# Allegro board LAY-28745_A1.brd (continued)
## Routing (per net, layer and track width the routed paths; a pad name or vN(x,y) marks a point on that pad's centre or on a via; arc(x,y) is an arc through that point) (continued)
DIO2: length 31.1
  TOP w0.152: U1.51 46.84,21.6 v1(46.82,21.62) ; R129.1 v1(49.24,43.97) 49.24,43.96 51.74,43.96 52.22,43.48 52.22,42.31 51.14,41.23 J18.3 51.14,39.24 50,38.1 50,33.68 v1(50.83,32.85)
  BOTTOM w0.152: v1(46.82,21.62) 46.82,21.88 48.22,23.27 48.22,25.48 50.83,28.09 v1(50.83,32.85) ; v1(49.24,43.97) TP45.1
DIO3: length 26.4
  TOP w0.152: v1(47.71,40.67) 47.71,39.27 v1(49.11,37.87) ; R130.1 v1(47.71,43.97) ; U1.52 46.34,21.09 v1(46.32,21.11)
  BOTTOM w0.152: v1(47.71,43.97) TP44.1 v1(47.71,40.67) ; v1(49.11,37.87) 49.36,37.62 49.36,32.51 48.76,31.9 48.76,27.5 47.76,26.5 47.76,23.34 46.32,21.89 v1(46.32,21.11)
DIO4: length 55.7
  TOP w0.152: v1(47.84,37.87) 46.95,38.76 v1(46.95,40.67) ; R131.1 v1(46.19,43.97) ; v1(59.78,44.73) 62.7,41.81 62.7,32.03 J10.1 ; U1.53 45.84,21.59 v1(45.81,21.62)
  BOTTOM w0.152: v1(47.84,37.87) 47.84,35.46 47.59,35.2 47.59,33.61 48.13,33.07 48.13,32.38 48.48,32.03 48.48,27.62 47.49,26.62 47.49,23.55 45.81,21.87 v1(45.81,21.62) ; v1(46.95,40.67) 46.95,42.19 TP43.1 v1(46.19,43.97) 46.95,44.73 53.05,44.73 53.56,44.22 54.06,44.22 54.57,44.73 v1(59.78,44.73)
DIO5/CLKOUT: length 12
  TOP w0.152: v1(45.3,21.11) 45.34,21.07 U1.54
  BOTTOM w0.152: v1(45.3,21.11) 45.3,19.35 44.5,18.56 44.5,15.34 43.2,14.04 41.15,14.04 TP42.1 41.11,12.85
EXTAL_32M: length 10.7
  TOP w0.152: C20.1 53.56,24.41 51.97,24.41 C21.1 49.79,25.04 Y1.1 49.35,24.7 48.35,23.7 48.35,22.44 49.34,21.45 U1.46
IO_REF: length 124.2
  TOP w0.203: U5.1 v1(3.77,24.92)
  TOP w0.305: U16.19 43.4,42.01 v1(43.4,44.73) ; U17.19 54.58,42.83 54.57,42.83 C62.1 v1(53.81,44.73)
  TOP w0.381: v1(41.11,45.75) 41.11,44.73 R125.1 41.62,44.73 C48.1 v1(43.4,44.73) ; R20.2 v1(8.85,26.44) ; R21.1 v1(7.07,22.63) ; v1(30.95,25.3) v1(27.9,25.3) ; R126.1 41.36,40.69 v1(41.84,41.16) ; v1(27.9,8.85) 27.9,12.85 v1(29.17,14.12) R139.1 R138.1 ; C64.1 v1(3.77,24.92)
  PWR w0.381: v1(41.84,41.16) 41.84,41.34 41.97,41.47 41.97,42.33 41.36,42.94 41.36,43.22 40.87,43.71 31.46,43.71 30.95,43.21 v1(30.95,42.7)
  BOTTOM w0.381: v1(27.9,8.85) 27.9,3.84 J3.4 ; v1(27.9,25.3) 12.41,25.3 11.26,26.44 v1(8.85,26.44) 7.96,25.55 7.96,23.52 v1(7.07,22.63) 6.31,21.87 4.28,21.87 3.77,22.38 v1(3.77,24.92) ; v1(30.95,42.7) v1(30.95,25.3) 30.95,22.57 31.2,22.31 31.2,16.03 R138.1 R139.1 v1(29.17,14.12) ; v1(43.4,44.73) 44.41,44.73 45.55,45.87 52.67,45.87 v1(53.81,44.73) ; v1(41.11,45.75) 41.11,45.24 42.77,43.58 42.77,42.1 v1(41.84,41.16)
P5-9V_VIN: length 28.9
  TOP w0.406: 38.06,6.63 38.06,1.8 38.7,1.17 40.47,1.17 J3.16 40.6,3.84 40.6,6.63
  TOP w0.813: J7.1 29.15,10.67 D1.A 29.2,7.95 C38.1 C39.1 C6.1 36.74,7.95 38.06,6.63 40.6,6.63
PA_BOOST: length 1.1
  TOP w0.203: U1.41 L12.1
PA_BOOST_EXT: length 4.5
  TOP w0.457: C1.1 L1.2 60.28,21.11 C2.1 60.29,21.11 C47.1
POWER_EN: length 6.3
  TOP w0.152: R551.1 26.44,44.16 26.44,42.28 26.45,42.27 26.45,41.61 v1(26.63,41.43) ; v1(26.63,40.39) U6.31
  BOTTOM w0.152: v1(26.63,41.43) v1(26.63,40.39)
PTA0/SWD_CLK: length 27.7
  TOP w0.152: U1.10 42.43,15.16 v1(42.28,15.31) ; v1(48.73,32.61) 48.29,32.17 48.29,30.44 J35.1 49.03,28.27 v1(47.45,28.27)
  BOTTOM w0.152: SH1.2 47.97,35.08 47.97,34.32 TP36.1 48.48,32.87 v1(48.73,32.61) ; v1(42.28,15.31) 43.53,16.55 43.53,18.96 43.66,19.1 43.66,19.1 44.06,19.5 44.06,22.48 44.52,22.95 45.48,22.95 46.58,24.05 46.58,26.59 46.58,26.59 46.58,27.4 v1(47.45,28.27)
PTA1/UART0_RX: length 53.3
  TOP w0.152: J41.2 60.67,30.76 60.67,32.28 62.19,33.81 v1(62.19,34.82) ; v1(32.79,37.49) 32.66,37.62 29.11,37.62 28.41,36.92 R89.2
  BOTTOM w0.152: v1(62.19,34.82) SH15.2 ; v1(32.79,37.49) 33.49,36.79 34.57,36.79 35.65,37.87 36.92,37.87 38.37,39.32 49.1,39.32 49.44,39.66 50.52,39.66 50.74,39.45 51.85,39.45 52.64,40.23 54.52,40.23 56.75,38 56.75,34.55 56.86,34.44 56.86,33.47 57.71,32.62 59.64,32.62 59.93,32.33 59.93,30.29 58.89,29.25 J41.2 TP113.1
PTA2/UART0_TX: length 44.6
  TOP w0.152: R88.2 31.71,36.6 v1(32.79,36.6) ; J42.1 57.87,33.05 60.03,33.05 60.67,33.68 v1(60.67,34.82)
  BOTTOM w0.152: v1(32.79,36.6) 33.24,36.16 35.78,36.16 36.09,36.47 36.09,37.17 36.41,37.49 36.98,37.49 38.53,39.04 49.19,39.04 49.52,38.71 50.29,38.71 50.47,38.89 51.49,38.89 52.22,38.16 52.22,34.51 54.44,32.28 55.59,32.28 J42.1 57.06,30.81 57.06,30.81 57.35,30.52 57.35,28.01 56.41,27.08 TP114.1 ; v1(60.67,34.82) SH16.2
PTA3/SWD_DIO: length 61.8
  TOP w0.152: v1(46,40.67) 46.57,40.09 v1(46.57,37.87) ; J14.2 v1(31.33,13.23) R25.1 ; U1.11 43.06,14.66 v1(42.9,14.49) 42.87,14.52 41.65,14.52 41.54,14.63 37.43,14.63 37.05,14.25 37.05,12.03 36.54,11.52 v1(33.62,11.52) ; R92.2 v1(37.55,45.75)
  BOTTOM w0.152: J14.2 33.62,13.11 v1(33.62,11.52) ; R25.1 v1(31.33,13.23) ; v1(42.9,14.49) 44.16,15.76 44.16,18.71 44.69,19.24 44.69,19.25 44.79,19.35 44.79,21.3 47.21,23.71 47.21,26.74 48.2,27.73 48.2,31.87 47.84,32.23 47.84,32.84 47.21,33.47 SH7.2 46.76,35.59 46.57,35.78 v1(46.57,37.87) ; v1(37.55,45.75) 37.55,44.48 38.06,43.97 40.28,43.97 40.7,43.56 40.7,41.08 41.07,40.7 45.96,40.7 v1(46,40.67)
PTA4/NMI: length 62.9
  TOP w0.152: v1(39.47,9.02) 39.49,9.04 41.24,9.04 R133.1 42.56,9.09 42.56,13.44 43.28,14.16 U1.12 ; v1(9.1,7.15) 9.09,7.14 R558.2 C53.1 SW4.1
  BOTTOM w0.152: v1(39.47,9.02) 39.47,7.61 38.09,6.24 38.09,1.95 37.67,1.52 18.26,1.52 12.46,7.32 12.46,10.05 11.55,10.97 11.55,10.97 11.49,11.03 7.34,11.03 6.8,10.49 6.8,7.74 7.41,7.14 TP29.1 9.09,7.14 v1(9.1,7.15)
PTA18: length 4.2
  TOP w0.152: U1.15 44.33,12.52 44.33,12.1 43.72,11.49 43.38,11.49 v1(43.23,11.34)
  BOTTOM w0.152: SH45.2 41.46,11.49 43.08,11.49 v1(43.23,11.34)
PTA19: length 83
  TOP w0.152: v1(42.63,8.36) 42.63,8.36 42.65,8.36 42.65,8.38 42.67,8.4 43.39,8.4 R136.1 43.78,8.79 43.78,11.06 44.84,12.12 U1.16
  BOTTOM w0.152: TP115.1 36.79,32.28 36.95,32.13 36.95,32.12 37.65,31.42 37.65,13.34 37.65,13.33 37.65,11.9 39.78,9.77 39.78,9.77 40.89,8.66 40.89,8.66 41.19,8.36 v1(42.63,8.36) 42.88,8.36 44.47,6.78 44.47,6.77 44.66,6.59 44.66,4.65 45.62,3.69 50.42,3.69 51,4.27 51,5.81 51.96,6.77 52.84,6.77 54.7,8.64 54.7,12.37 54.21,12.87 53.76,12.87 52.38,14.25 52.06,14.25 51.75,14.56 51.75,17.4 52.76,18.41 54.74,18.41 55.16,18 56.13,18 56.91,18.78 56.91,19.3 57.5,19.89 60.32,19.89 62.71,22.28 62.71,28.06 62.19,28.58 J10.2
PTB0: length 37.4
  TOP w0.152: R29.2 v1(36.54,31.52) ; U1.17 45.34,12.19 44.16,11.01 44.16,9.17 44.67,8.66 44.67,8.66 R132.1 44.01,7.5 v1(44.01,6.59)
  BOTTOM w0.152: v1(44.01,6.59) 44.01,6.59 44.01,6.59 44.02,6.59 44.02,6.6 43.99,6.6 43.99,6.6 44.02,6.6 44.02,6.63 42.75,7.91 41.25,7.91 40.84,8.31 40.84,8.31 40.84,8.32 40.78,8.38 40.77,8.38 39.5,9.65 39.5,9.65 39.5,9.65 37.37,11.79 37.37,13.45 37.37,13.45 37.37,29.67 TP120.1 v1(36.54,31.52)
PTB1: length 79
  TOP w0.152: R28.2 37.35,33.61 37.35,34.1 37.76,34.51 38.38,34.51 38.78,34.11 38.78,33.53 39.29,33.02 41.7,33.02 41.96,33.28 42.41,33.28 42.76,32.93 42.76,32.46 42.67,32.38 42.67,32.38 42.63,32.34 42.63,32.34 42.43,32.13 42.43,28.18 42.99,27.62 44.94,27.62 45.48,28.17 45.48,29.38 46.04,29.95 47.64,29.95 47.93,30.24 47.93,32.52 48.49,33.08 48.91,33.08 49.64,33.81 49.64,38.7 v1(50.1,39.17) 50.1,41.91 J18.4 ; U1.18 45.84,13.01 46.06,13.23 47.43,13.23 47.74,13.54 47.74,15.54 48.29,16.09 v2(48.22,16.09)
  BOTTOM w0.152: v1(50.1,39.17) 52.06,39.17 52.84,39.95 54.41,39.95 55.61,38.75 55.61,37.32 55.47,37.18 55.47,35.81 55.7,35.59 SH11.2 TP121.1 57.65,32.26 57.65,27.2 56.18,25.74 55.27,25.74 55.06,25.54 53.49,25.54 53.49,25.54 53.11,25.54 53.11,25.54 50.62,25.54 49.75,24.66 49.75,21.03 47.68,18.96 47.68,18.96 47.68,16.64 v2(48.22,16.09)
PTB2: length 67.8
  TOP w0.152: v2(49.25,16.12) 48.84,15.71 48.45,15.71 48.02,15.28 48.02,13.41 47.34,12.73 U1.21 ; v1(32.79,35.59) 31.71,35.59 R91.2
  BOTTOM w0.152: v2(49.25,16.12) 49.25,16.33 49.09,16.5 49.09,17.43 49.49,17.84 49.49,18.43 49.41,18.51 49.41,18.97 50.4,19.95 51.44,19.95 53.39,21.9 53.81,21.9 54.44,22.54 54.44,24.09 55.46,25.11 58,25.11 59.64,26.75 59.64,28.2 60.21,28.77 60.21,32.44 59.75,32.9 58.53,32.9 TP123.1 SH12.2 57.24,35.59 57.03,35.79 57.03,38.12 54.64,40.52 52.56,40.52 51.7,41.38 50.74,41.38 48.96,39.6 36.61,39.6 35.9,38.89 34.89,38.89 34.51,39.27 33.55,39.27 32.28,38 32.28,36.09 v1(32.79,35.59)
PTB17: length 74.2
  TOP w0.152: v1(32.79,34.7) 29.04,34.7 R90.2 ; v2(48.73,14.19) 48.3,13.75 48.3,13.2 47.84,12.73 U1.22
  BOTTOM w0.152: v1(32.79,34.7) 31.97,35.52 31.97,38.25 33.36,39.65 34.63,39.65 35.01,39.27 35.8,39.27 36.41,39.88 48.85,39.88 50.62,41.66 51.88,41.66 52.72,40.83 54.73,40.83 57.24,38.32 58.62,38.32 59.79,37.15 59.79,35.78 59.59,35.59 SH14.2 TP122.1 59.26,33.81 60.49,32.57 60.49,28.64 59.93,28.09 59.93,27.33 60.21,27.05 60.21,23.64 58.15,21.57 53.46,21.57 50.21,18.33 50.21,17.99 49.37,17.14 49.37,16.61 49.68,16.3 49.68,15.94 49.17,15.43 49.17,14.63 v2(48.73,14.19)
PTC1: length 41.9
  TOP w0.152: v1(62.2,27.79) 61.97,27.79 61.56,28.2 59.74,28.2 59.32,27.77 55.78,27.77 54.57,28.98 v1(54.57,32.85) ; R97.2 54.06,12.22 v1(54.08,12.23)
  BOTTOM w0.152: v1(54.08,12.23) 53.9,12.23 53.11,13.02 53.11,13.03 52.23,13.9 51.92,13.9 51.41,14.41 51.41,17.55 52.62,18.76 54.89,18.76 55.31,18.34 55.98,18.34 56.57,18.92 56.57,19.45 57.39,20.27 60.21,20.27 62.36,22.42 62.36,27.6 62.19,27.77 62.19,27.79 v1(62.2,27.79) ; v1(54.57,32.85) TP112.1 SH10.2
PTC1/RTC_IN: length 5.8
  TOP w0.152: R97.1 52.61,10.76 52.28,10.76 52.27,10.77 50.77,10.77 50.65,10.65 49.7,10.65 49.19,11.16 49.19,11.56 48.84,11.91 U1.24
PTC2: length 122.2
  TOP w0.152: v1(62.19,38.82) 62,39.01 59.08,39.01 58.53,38.46 54.59,38.46 v1(54.57,38.44) ; v1(54.49,6.7) 54.47,6.7 54.47,6.77 54.14,7.1 54.14,7.89 53.61,8.42 v1(53.61,8.55) ; v1(9.1,10.18) 9.09,10.19 R557.2 C52.1 6.31,10.19 5.85,10.64 SW3.1 ; U1.25 49.34,13.01 49.56,13.23 50.63,13.23 50.81,13.41 50.81,14.81 50.72,14.9 50.72,14.92 50.6,15.04 50.58,15.04 v2(50.43,15.19)
  BOTTOM w0.152: TP24.1 9.09,10.19 v1(9.1,10.18) 9.1,10.18 9.67,10.75 11.37,10.75 12.16,9.96 12.16,7.19 15,4.34 15,4.32 18.15,1.18 53.26,1.18 53.6,1.52 53.6,5.91 54.39,6.7 v1(54.49,6.7) ; SH9.2 53.56,35.59 53.87,35.9 53.87,37.62 54.57,38.32 v1(54.57,38.44) ; v1(53.61,8.55) 53.48,8.67 53.48,9.51 52.65,10.34 52.65,12.6 52.49,12.76 52.49,12.77 51.97,13.28 51.66,13.28 50.58,14.36 50.58,14.66 50.43,14.82 v2(50.43,15.19) 50.78,15.54 50.78,17.89 53.89,21 59.45,21 60.79,22.34 60.79,27.32 61,27.52 61,28.35 60.79,28.55 60.79,32.66 59.92,33.54 59.92,35.05 60.12,35.25 60.12,37.61 59.96,37.77 59.96,38.49 60.29,38.82 v1(62.19,38.82)
PTC3: length 5.3
  TOP w0.152: v1(49.74,11.68) 49.84,11.78 U1.26
  BOTTOM w0.152: SH40.2 47.71,9.58 47.48,9.81 47.48,10.29 48.16,10.98 48.16,11.48 48.44,11.76 49.66,11.76 v1(49.74,11.68)
PTC4: length 5.2
  TOP w0.152: U1.23 48.34,11.72 48.73,11.33 v1(48.73,11.3)
  BOTTOM w0.152: SH41.2 48.2,8.15 48.72,8.68 48.72,11.29 v1(48.73,11.3)
PTD4/SPI1_PCS0: length 45
  TOP w0.152: U1.27 50.34,11.8 50.34,11.8 50.34,11.14 v1(50.34,11.13)
  BOTTOM w0.152: SH3.2 45.94,34.98 46.92,33.99 46.92,33.35 47.55,32.73 47.55,32.12 47.92,31.75 47.92,27.85 46.93,26.86 46.93,23.89 45.62,22.58 44.73,22.58 44.46,22.31 44.46,22.3 44.4,22.25 44.4,19.35 43.87,18.82 43.87,16.12 42.49,14.74 40.74,14.74 40.56,14.56 40.55,14.56 40.14,14.15 40.14,11.9 40.94,11.1 40.97,11.1 40.99,11.08 42.7,11.08 46.23,7.55 48.12,7.55 49.18,8.61 49.18,9.97 v1(50.34,11.13)
PTD5/SPI1_SCK: length 45.7
  TOP w0.152: v1(50.91,11.71) 50.84,11.78 U1.28
  BOTTOM w0.152: SH6.2 44.67,35.22 45.38,34.5 45.38,33.01 45.04,32.67 45.04,28.73 41.55,25.24 41.55,19.32 42.35,18.52 42.35,16.68 41,15.33 40.45,15.33 39.57,14.46 39.57,11.66 40.76,10.47 42.07,10.47 42.07,10.47 42.48,10.47 45.98,6.96 49.28,6.96 49.51,7.19 49.51,9.18 v1(50.11,9.78) 50.61,10.28 50.61,10.28 51.08,10.75 51.08,11.54 v1(50.91,11.71)
PTD6/LLWU_P15: length 99.6
  TOP w0.152: R134.1 53.02,7.93 v1(53.18,7.93) ; v1(39.27,29.05) 39.25,29.03 39.25,27.95 39,27.7 39,27.7 38.95,27.65 37.16,27.65 36.95,27.86 36.11,27.86 34.95,26.7 v1(27.94,26.7) ; v1(52.03,11.33) 51.46,11.9 51.46,12.51 51.46,12.51 51.46,13.07 51.46,13.07 U1.29 ; SW1.1 5.85,47.09 6.44,46.51 C51.1 R556.2 8.5,46.51 9,46.01 v1(9.04,46.01)
  BOTTOM w0.152: v1(27.94,26.7) 27.4,27.24 13.69,27.24 9.98,30.94 9.98,38.56 9.04,39.5 v1(9.04,46.01) 9.04,46.04 8.49,45.49 TP23.1 ; v1(39.27,29.05) 39.27,28.57 38.65,27.95 38.65,11.29 41.11,8.83 42.81,8.83 42.98,8.66 42.98,8.66 44.75,6.89 44.75,6.89 44.94,6.7 44.94,4.77 45.73,3.97 50.3,3.97 50.71,4.37 50.71,5.92 51.95,7.16 52.4,7.16 53.17,7.93 ; 53.17,7.93 53.17,7.94 53.17,8.16 53.18,8.17 53.18,8.36 52.54,9 52.53,9 52.35,9.19 52.35,11.01 v1(52.03,11.33) ; 53.17,7.93 v1(53.18,7.93)
PTD7: length 108.7
  TOP w0.152: U1.31 52,14.16 52.27,13.89 52.27,13.89 52.56,13.6 v1(53.68,13.6) ; SW2.1 6.36,42.19 C54.1 R559.2 v1(11.78,42.19) ; v1(62.19,39.52) 62,39.33 57.52,39.33 57.5,39.35 v1(57.19,39.35) 57.2,39.33 v1(53.87,39.33)
  BOTTOM w0.152: v1(53.68,13.6) 53.6,13.68 53.6,13.74 52.79,14.55 52.19,14.55 52.03,14.71 52.03,17.29 52.88,18.14 54.49,18.14 54.92,17.7 56.23,17.7 57.19,18.67 57.19,19.16 57.64,19.61 60.43,19.61 62.99,22.16 62.99,28.32 63.27,28.6 63.27,32.35 62.95,32.66 62.95,38.76 v1(62.19,39.52) ; TP30.1 v1(11.78,42.19) 13.49,42.19 14.48,43.18 15.83,43.18 18.38,45.73 20.17,45.73 20.24,45.79 20.62,45.79 20.68,45.73 22.6,45.73 23.03,46.16 29.78,46.16 30.21,46.59 35.86,46.59 36.22,46.23 36.22,44.01 38.22,42.01 39.29,42.01 41.14,40.16 48.73,40.16 50.52,41.95 52.12,41.95 52.12,41.95 52.13,41.95 52.13,41.94 52.13,41.93 52.14,41.92 52.14,41.92 52.15,41.9 52.16,41.9 52.25,41.81 52.25,41.8 52.34,41.72 52.34,41.72 52.93,41.13 54.86,41.13 56.3,39.69 56.85,39.69 v1(57.19,39.35) ; SH8.2 v1(53.87,39.33)
PTE0/SPI1_MISO: length 54.5
  TOP w0.152: v1(54.05,14.22) 54.03,14.21 52.79,14.21 52.34,14.66 U1.32 ; v1(51.79,7.96) 51.79,7.27 v1(52.79,6.27)
  BOTTOM w0.152: v1(51.79,7.96) 51.39,8.36 50.13,8.36 49.87,8.09 49.87,7.04 49.45,6.62 45.83,6.62 42.96,9.49 41.37,9.49 40.66,10.2 40.64,10.2 39.28,11.55 39.28,14.56 40.34,15.62 40.86,15.62 42.07,16.83 42.07,18.4 41.4,19.07 40.78,19.07 40.1,19.74 40.1,25.68 42.7,28.27 42.7,28.31 42.74,28.35 42.74,30.38 43.87,31.52 J44.1 ; v1(52.79,6.27) 52.79,6.33 55,8.53 55,13.46 54.24,14.22 v1(54.05,14.22)
PTE1/SPI1_MOSI: length 37.5
  TOP w0.152: v1(50.17,16.08) 50.59,15.66 U1.34 ; J43.2 46.44,28.36 47.19,27.62 50.26,27.62 52.57,29.93 52.63,29.93 52.65,29.95 53.48,29.95 54.06,29.36 54.06,28.99 55.67,27.39 60.23,27.39 60.48,27.64 v1(60.48,27.74)
  BOTTOM w0.152: v1(50.17,16.08) 50.17,16.57 50.49,16.89 50.49,18.04 53.75,21.29 58.3,21.29 60.52,23.51 60.52,27.67 60.48,27.71 v1(60.48,27.74)
PTE16: length 92.7
  TOP w0.152: v1(42.85,17.67) 43.25,17.67 43.26,17.66 U1.5 ; v1(48.68,7.42) 48.68,7.59 R137.1 50.06,8.98 50.52,8.98 50.54,9 53.41,9 53.42,9 53.8,9 53.8,9 54.15,9 v1(54.21,8.93) ; R11.2 v1(33.49,33.17)
  BOTTOM w0.152: v1(33.49,33.17) 33.49,34.44 33.93,34.89 37.93,34.89 v1(38.38,35.33) 38.38,37.06 38.88,37.57 43.06,37.57 43.84,38.35 44.82,38.35 45.39,37.78 45.39,34.93 45.68,34.64 45.68,32.89 45.34,32.55 45.34,28.6 41.83,25.09 41.83,19.43 42.85,18.42 v1(42.85,17.67) 42.86,17.66 42.86,16.78 41.13,15.05 40.6,15.05 39.85,14.31 39.85,11.78 40.87,10.76 42.6,10.76 46.11,7.25 48.51,7.25 v1(48.68,7.42) ; TP119.1 61.18,26.7 61.18,21.97 59.83,20.62 57.24,20.62 56.22,19.6 56.22,19.06 55.84,18.68 55.45,18.68 55.03,19.1 52.47,19.1 51.06,17.7 51.06,15.42 51.06,15.42 51.06,14.28 51.78,13.56 52.09,13.56 52.77,12.88 52.77,12.88 52.95,12.7 52.95,10.51 54.04,9.42 54.04,9.1 v1(54.21,8.93)
PTE17: length 48.1
  TOP w0.152: v1(41.28,18.37) 42.49,17.16 U1.6 ; v1(50.33,7.91) 50.83,8.41 R135.1 ; v1(42.25,32.73) 42.25,32.72 39.14,32.72 38.06,33.8 R30.2
  BOTTOM w0.152: v1(42.25,32.73) 42.42,32.56 42.42,28.39 39.81,25.78 39.81,19.2 40.65,18.37 v1(41.28,18.37) 41.51,18.13 41.51,16.7 40.72,15.91 40.15,15.91 38.97,14.73 38.97,11.37 41.19,9.15 42.89,9.15 43.1,8.94 43.1,8.94 45.24,6.8 45.24,6.8 45.72,6.31 49.73,6.31 50.33,6.91 v1(50.33,7.91)
PTE18/I2C0_SDA: length 27.2
  TOP w0.152: v1(40.09,36.09) R119.1 40.09,38.13 R117.2 ; v1(41.04,17.47) 41.09,17.47 41.89,16.66 43.71,16.66 U1.7 ; v1(41.36,32.03) 41.25,31.92 Q1.S2
  BOTTOM w0.152: v1(40.09,36.09) 40.22,35.97 40.22,33.17 v1(41.36,32.03) 41.36,27.76 39.53,25.92 39.53,18.97 41.04,17.47 v1(41.04,17.47)
PTE19/I2C0_SCL: length 31.2
  TOP w0.152: v1(39.33,35.33) R118.1 40.09,34.06 R116.2 ; v1(40.74,16.85) 40.93,16.85 41.62,16.15 42.38,16.15 42.38,16.16 U1.8 ; v1(39.84,29.74) 39.97,29.62 39.97,28.71 Q1.S1 39.95,28.12 39.03,27.2 v1(36.54,27.2)
  BOTTOM w0.152: v1(40.74,16.85) 40.74,16.85 40.52,17.07 40.52,17.38 39.24,18.65 39.24,26.05 40.46,27.26 40.46,29.12 v1(39.84,29.74) 39.33,30.25 v1(39.33,35.33)
PTE30: length 2.3
  TOP w0.152: U1.9 42.58,15.66 42.47,15.76 42.09,15.76 41.99,15.66 41.5,15.66 R85.1
RESET_B_TGTMCU: length 6.7
  TOP w0.152: U6.21 23.58,36.22 24.6,35.2 26.63,35.2 27.27,34.57 27.27,33.68 J11.2
RESET_B_XCVR: length 24
  TOP w0.152: R5.1 42.51,24.98 44.59,27.06 51.32,27.06 v1(52.03,27.77) ; U1.48 48.34,21.1 v1(48.35,21.11)
  BOTTOM w0.152: J31.1 52.03,30.51 v1(52.03,27.77) 51.9,27.77 49.14,25.01 49.14,21.9 v1(48.35,21.11)
RESET_TGTMCU_B: length 110.1
  TOP w0.152: J9.3 3.26,22.12 R14.2 ; J14.10 33.49,24.92 32.47,25.93 v1(27.27,25.93) ; 21.81,24.73 22.76,24.73 23.2,25.17 v1(23.2,25.93) ; 21.81,24.73 D5.C ; 21.81,24.73 R13.2 21.3,22.63 U3.7 ; v1(52.6,15.11) 52.55,15.16 U1.33 ; R124.1 5.8,26.7 v1(5.8,26.44) U5.7 ; v1(38.19,8.41) 39.69,8.41 v1(40.05,8.05)
  BOTTOM w0.152: v1(27.27,25.93) v1(23.2,25.93) 13.8,25.93 12.53,27.2 6.57,27.2 v1(5.8,26.44) 5.3,26.95 3.52,26.95 3.26,26.7 TP35.1 J9.3 ; v1(52.6,15.11) 52.92,15.43 53.7,15.43 54.98,14.15 54.98,13.87 55.28,13.58 55.28,13.35 55.28,13.34 55.28,8.42 53.29,6.43 53.29,1.81 52.98,1.5 40.97,1.5 40.63,1.83 40.63,5.77 40.04,6.36 40.04,8.04 v1(40.05,8.05) ; J14.10 32.79,18.31 31.84,17.36 31.84,12.79 33.11,11.52 33.11,8.85 33.55,8.41 v1(38.19,8.41)
RFIO: length 1.1
  TOP w0.203: U1.39 L9.1
RFIO_EXT: length 8.6
  TOP w0.203: C7.1 L2.2 59.52,15.4 C4.1
  TOP w0.457: C4.1 C50.1
RXTX: length 41.9
  TOP w0.152: R141.1 v1(58.51,43.97) ; U1.37 52.55,17.16 v1(52.72,17.33)
  BOTTOM w0.152: v1(58.51,43.97) 58.52,43.98 60.92,43.98 63.92,40.98 63.92,21.28 61.25,18.61 57.71,18.61 55.83,16.73 55.45,16.73 54.75,17.42 TP37.1 52.82,17.42 v1(52.72,17.33)
SDA_EXTAL: length 3.9
  TOP w0.152: U6.17 21.55,36.74 21.55,36.09 C31.1 20.66,35.2 20.66,34.04 Y3.3
SDA_JTAG_TCLK: length 11.9
  TOP w0.152: U6.12 20.93,39.37 v1(19.77,39.37)
  BOTTOM w0.152: v1(19.77,39.37) 18.99,39.37 18.76,39.14 18.76,38.63 19.27,38.13 19.27,36.98 18.76,36.47 18.76,32.92 TP509.1 J13.4
SDA_JTAG_TDI: length 14.6
  TOP w0.152: U6.13 19.27,38.89 v1(19.27,38.89)
  BOTTOM w0.152: v1(19.27,38.89) 20.03,38.89 20.28,38.63 20.28,31.9 TP511.1 J13.8
SDA_JTAG_TDO: length 11.2
  TOP w0.152: U6.14 19.79,38.39 v1(19.77,38.38)
  BOTTOM w0.152: J13.6 TP510.1 19.14,32.03 19.14,36.35 19.77,36.98 v1(19.77,38.38)
SDA_JTAG_TMS: length 12.2
  TOP w0.152: J13.2 16.09,36.86 R107.2 ; U6.15 19.28,37.89 19.27,37.87 v1(18.76,37.87)
  BOTTOM w0.152: v1(18.76,37.87) 18.76,36.98 18.38,36.6 18.38,33.81 TP508.1 J13.2
SDA_LED: length 3.7
  TOP w0.152: v1(27.52,40.41) 27.52,39.78 27.14,39.4 D11.C 27.12,39.39 U6.29
  BOTTOM w0.152: TP106.1 27.52,39.52 v1(27.52,40.41)
SDA_RST: length 16.3
  TOP w0.152: v1(24.09,31.27) R100.1 R52.2 23.58,34.32 v1(23.58,34.82) 23.58,34.95 22.58,35.95 U6.19
  BOTTOM w0.152: J13.10 TP512.1 18.76,29.11 21.93,29.11 v1(24.09,31.27) ; TP105.1 v1(23.58,34.82)
SDA_RST_TGTMCU_J_B: length 43
  TOP w0.152: R14.1 4.53,21.87 7.07,21.87 J9.1 9.36,21.62 v1(16.09,21.62) ; R16.2 v1(20.03,18.82) 20.66,18.19 22.44,18.19 23.33,19.08 23.33,21.74 23.96,22.38 26.5,22.38 27.01,22.89 27.01,24.03 27.52,24.54 v1(29.43,24.54) ; v1(20.03,20.09) 20.9,20.09 U3.2
  BOTTOM w0.152: J11.1 29.43,28.98 v1(29.43,24.54) ; v1(16.09,21.62) 16.09,20.47 16.47,20.09 v1(20.03,20.09) v1(20.03,18.82)
SDA_SPI0_SCK: length 13.6
  TOP w0.152: U4.12 34.89,42.63 34.89,38.51 34.44,38.06 27.58,38.06 v1(27.39,37.87) 25.73,37.87 U6.26
SDA_SPI0_SIN: length 17.4
  TOP w0.152: v1(34.25,40.67) 34.25,39.9 33.11,38.76 26.44,38.76 26.31,38.89 U6.28 ; R112.1 37.47,43.89 U4.8 37.43,42.64 v1(37.43,40.67)
  BOTTOM w0.152: v1(37.43,40.67) v1(34.25,40.67)
SDA_SPI0_SOUT: length 11.7
  TOP w0.152: v1(34.25,38.63) 34.06,38.44 25.73,38.44 U6.27 ; v1(34.25,37.49) 34.25,35.67 U4.2
  BOTTOM w0.152: v1(34.25,37.49) v1(34.25,38.63)
SDA_SWD_EN: length 23.1
  TOP w0.152: U6.16 20.79,37.39 v1(20.79,36.6) ; v1(28.41,40.41) 30.44,40.41 R106.2 v1(34.25,41.43) 34.22,41.46 U4.13 ; v1(36.16,41.43) 36.17,41.44 U4.10
  BOTTOM w0.152: v1(36.16,41.43) v1(34.25,41.43) ; v1(20.79,36.6) 21.17,36.22 27.77,36.22 28.41,36.86 v1(28.41,40.41)
SDA_SWD_OE_B: length 17.8
  TOP w0.152: U4.1 33.57,34.14 33.24,33.81 v1(32.79,33.81) R105.1 31.71,32.03 31.33,31.65 27.27,31.65 26.89,32.03 26.89,34.32 26.38,34.82 24.47,34.82 23.08,36.22 23.08,36.74 U6.20
SDA_USB_CONN_DN: length 24.7
  TOP w0.292: v1(23.47,45) 23.56,44.92 23.56,44.45 R50.1 ; v1(10.91,34.98) 10.94,34.98 10.94,35.06 10.88,35 10.56,35 U12.1 9.61,34.93 8.76,34.93 8.58,35.12 J15.2
  BOTTOM w0.292: v1(10.91,34.98) 10.93,34.98 10.92,34.97 10.92,34.97 10.93,34.96 11.26,34.96 11.65,35.35 11.65,36.15 14.7,39.2 14.7,39.2 18.5,43 18.5,43 18.59,43.09 19.98,43.09 19.98,43.09 20.47,43.09 20.47,43.09 21.04,43.09 22.18,41.94 22.82,41.94 23.6,42.72 23.6,43.07 23.61,43.07 23.61,44.87 v1(23.47,45)
SDA_USB_CONN_DP: length 25.4
  TOP w0.292: v1(24.13,45) 24.13,44.94 24.04,44.85 24.04,44.53 R51.1 ; J15.3 8.58,34.32 8.77,34.5 9.57,34.5 U11.1 10.12,33.99 10.52,34.38 10.87,34.38 v1(10.93,34.32)
  BOTTOM w0.292: v1(24.13,45) 24.04,44.91 24.04,42.54 23,41.51 22,41.51 20.86,42.65 18.77,42.65 15.14,39.02 15.14,39.02 12.09,35.97 12.09,35.17 11.42,34.5 11.2,34.5 11.02,34.32 v1(10.93,34.32)
SDA_USB_DN: length 1.8
  TOP w0.254: U6.4 23.58,41.92 23.63,41.97 23.63,42.9 R50.2
SDA_USB_DP: length 1.8
  TOP w0.254: R51.2 24.03,42.89 24.03,41.97 24.08,41.92 U6.3
SDA_USB_VOUT33: length 48
  TOP w0.203: C32.1 21.55,43.69 21.85,43.99 21.85,44.2 21.84,44.2 21.84,44.41 v1(21.83,44.42) ; C32.1 21.55,42.41 22.08,41.88 U6.7 ; C32.1 22.24,43.46 23.08,42.62 U6.5 ; C29.1 19.27,20.65 19.47,20.85 U3.1 ; v1(19.27,39.9) 19.28,39.89 U6.11
  TOP w0.254: v1(24.85,42.45) 24.85,42.34 25.08,42.11 U6.1
  TOP w0.305: 19.27,19.46 20.54,19.46 20.79,19.2 R19.2 ; 19.27,19.46 18.25,19.46 ; 19.27,19.46 C29.1 ; 18.25,19.46 R16.1 ; 18.25,19.46 17.21,19.46
  TOP w0.406: U4.14 33.57,42.7 v1(32.73,42.7) ; U4.4 v1(35.52,36.86)
  TOP w0.508: C66.1 v1(19.27,39.9) ; R17.1 v1(32.35,39.4) ; R105.2 v1(29.3,33.81) ; J13.1 v1(14.82,34.57) ; R106.1 v1(29.17,41.43) R110.1 ; v1(24.85,42.45) 24.86,42.45 25.36,42.95 C26.1 ; R107.1 14.82,36.86 v1(14.82,35.84)
  TOP w0.762: v3(17.49,36.86) 18,36.35 18,27.27 17.21,26.48 D7.A
  PWR w0.508: 13.46,34.3 J13.1
  BOTTOM w0.508: v1(24.85,42.45) 24.85,42.44 TP103.1
SDA_USBSHIELD: length 19.8
  TOP w0.508: v1(4.91,29.87) 4.91,29.87 ; J15.S3 1.86,39.97 ; J15.S3 1.86,37.56 ; J15.S3 3.32,38.77 ; 9.91,29.03 L7.1 ; L7.1 9.04,30 ; L7.1 9.91,30.96 ; J15.S2 7.36,31.07 ; J15.S2 8.82,29.87 ; J15.S2 7.36,28.66 ; J15.S2 5.9,29.87 ; 7.36,37.56 J15.S1 ; J15.S1 7.36,39.97 ; J15.S1 5.9,38.77 ; J15.S4 3.32,29.87 ; J15.S4 1.86,31.07 ; J15.S4 1.86,28.66
SDA_XTAL: length 10.3
  TOP w0.152: U6.18 22.08,35.86 21.3,35.08 21.3,31.01 22.5,29.81 ; Y3.1 22.5,29.81 ; 22.5,29.81 22.5,30.18 22.82,30.51 C30.1
SW1_RST_B: length 6.4
  TOP w0.152: R113.2 C60.1 5.85,17.3 ; 5.85,17.3 5.85,20.6 J9.2 ; 5.85,17.3 SW5.1
SWD_CLK_TGTMCU: length 63.5
  TOP w0.152: v1(31.52,24.54) 31.84,24.22 31.84,15.39 32.73,14.5 J14.4 ; v1(34.25,45.75) R93.2 ; v1(38.06,41.43) v1(38.06,37.87)
  BOTTOM w0.152: J35.2 49.75,38 49.05,38.7 43.7,38.7 42.92,37.92 38.11,37.92 v1(38.06,37.87) ; v1(38.06,41.43) 35.87,43.62 35.87,45.14 R93.2 v1(34.25,45.75) 31.52,43.01 v1(31.52,24.54)
SWD_CLK_TGTMCU_R: length 4.9
  TOP w0.152: R93.1 35.52,44.48 U4.11 v1(35.52,39.9)
SWD_DIO_TGTMCU: length 10.4
  TOP w0.152: R92.1 36.82,44.73 U4.9 36.79,42.64 v1(36.79,38.63) 36.03,38.63 34.87,37.48 U4.3
TC_EXTAL_TP: length 5
  TOP w0.152: U6.10 19.73,40.39 19.2,40.92 v1(18.5,40.92)
  BOTTOM w0.152: TP102.1 19.01,40.41 v1(18.5,40.92)
TC_SDA_USB_ID_TP: length 2.7
  TOP w0.152: v1(5.8,33.55) 7.45,33.55 J15.4
  BOTTOM w0.152: TP100.1 v1(5.8,33.55)
TC_XTAL_TP: length 2.9
  TOP w0.152: v1(19.65,41.68) 19.65,41.24 19.99,40.89 U6.9
  BOTTOM w0.152: TP101.1 v1(19.65,41.68)
UART1_CTS_TGTMCU: length 5
  TOP w0.152: U6.22 24.08,36.23 24.73,35.59 27.14,35.59 R90.1 27.39,35.2 v1(27.9,34.7)
UART1_RST_TGTMCU: length 6.7
  TOP w0.152: U6.23 24.58,36.24 24.92,35.9 28.73,35.9 v1(29.3,35.33) R91.1
UART1_RX_TGTMCU: length 1.9
  TOP w0.152: U6.25 26.1,37.39 v1(26.63,36.86) R89.1
UART1_TX_TGTMCU: length 6
  TOP w0.152: U6.24 25.08,36.44 25.3,36.22 28.66,36.22 v1(29.3,36.86) R88.1
V_EXT: length 2.8
  TOP w0.813: D2.A 20.28,7.88 J28.1
V_MCU: length 41.9
  TOP w0.203: U3.8 20.9,21.62 v1(20.03,21.62)
  TOP w0.254: C43.1 46.34,11.73 U1.19 ; v1(44.92,22.12) 44.92,21.59 44.67,21.34 44.67,20.98 44.84,20.81 U1.55
  TOP w0.305: v1(56.35,13.87) 56.3,13.91 Y4.1 ; Y4.12 57.16,13.91 v1(57.11,13.87)
  TOP w0.508: v1(36.41,13.23) J14.1 34.76,12.66 34.32,12.22 29.81,12.22 29.3,12.73 R25.2 ; R13.1 C35.1 C59.1 v1(20.03,21.62) ; R9.2 39.6,23.54 40.94,23.54 v1(40.98,23.58) R5.2 ; C43.1 v1(45.17,11.33) ; v1(44.92,22.12) C42.1 43.84,22.12 v1(43.4,21.68) 42.13,21.68 C27.1 ; R18.2 v1(19.27,23.9) ; R113.1 v1(9.11,16.28)
  PWR w0.457: v1(9.11,16.28) 15.07,16.28
  PWR w0.508: 24.38,24.63 J40.1 ; J40.1 26.34,22.67 ; J40.1 24.38,22.67 ; J40.1 26.34,24.63
  BOTTOM w0.508: TP6.1 J40.1 ; SH42.1 v1(43.4,21.68)
V_RF: length 7.8
  TOP w0.203: v1(52.49,16.16) 52.49,16.16 U1.35
  TOP w0.254: v1(51.39,20.6) 51.15,20.6 U1.43
  TOP w0.508: C19.1 52.99,16.66 52.87,16.54 52.85,16.54 52.83,16.52 52.79,16.52 52.76,16.49 52.74,16.49 52.61,16.36 52.61,16.34 52.58,16.31 52.58,16.27 52.57,16.25 52.57,16.24 v1(52.49,16.16) ; C25.1 v1(51.39,20.6)
  PWR w0.508: J47.1 30.15,19.55
  BOTTOM w0.508: TP13.1 J47.1
VR_ANA: length 5
  TOP w0.254: v1(52.35,21.62) 51.84,21.11 50.52,21.11 50.34,20.92 U1.44
  TOP w0.508: C44.1 v1(52.35,21.62)
  BOTTOM w0.508: v1(52.35,21.62) TP46.1
VR_DIG: length 4.1
  TOP w0.254: U1.45 49.84,21.1 50.36,21.62 v1(50.89,21.62)
  TOP w0.508: C28.1 v1(50.89,21.62)
  BOTTOM w0.508: v1(50.89,21.62) TP48.1
VR_PA: length 10.5
  TOP w0.254: U1.42 52.11,19.66 52.29,19.84 v1(53.56,19.84)
  TOP w0.457: 55.65,18.19 54.95,18.19 L11.1 ; 55.65,18.19 v1(55.65,19.14) ; 55.65,18.19 56.36,18.19 C16.1 56.35,18.15 C14.1 ; v1(55.65,19.14) 56.36,19.14 C18.1 56.35,19.16 C17.1 ; v1(55.65,19.14) 54.95,19.14 L10.1
  BOTTOM w0.381: v1(53.56,19.84) 54.95,19.84 v1(55.65,19.14)
VTRG_EN: length 7.6
  TOP w0.152: v1(21.81,47.02) 22.31,46.51 R109.1 ; R109.1 R108.2 ; R109.1 R551.2 25.86,46.25 26.64,45.47 U7.3
VTRG_FAULT_B: length 4.8
  TOP w0.152: v1(27.14,44.22) 27.46,43.9 U7.4 27.43,42.94 27.43,42.17 27.39,42.14 R110.2 26.86,40.89 U6.32
XCVR-SPI_CLK: length 1.7
  TOP w0.152: U1.59 49.1,13.42 v2(48.73,13.42)
  BOTTOM w0.152: v2(48.73,13.42) TP38.1
XCVR-SPI_MISO: length 4.2
  TOP w0.152: U1.57 49.27,14.66 v2(48.73,15.2)
  BOTTOM w0.152: v2(48.73,15.2) 48.22,14.69 48.22,13.49 TP39.1
XCVR-SPI_MOSI: length 2.6
  TOP w0.152: U1.60 v2(49.81,14.19)
  BOTTOM w0.152: TP41.1 49.81,12.92 v2(49.81,14.19)
XCVR-SPI_SS_B: length 4.6
  TOP w0.152: v2(49.61,15.22) 50.17,14.66 U1.58
  BOTTOM w0.152: v2(49.61,15.22) 50.29,14.54 50.29,13.96 TP40.1
XTAL_32M: length 4.7
  TOP w0.152: SH44.1 46.25,22.19 48.09,22.19 48.84,21.44 U1.47
N23353475: length 2.2
  TOP w0.152: C20.2 J5.1
N23353504: length 2.9
  TOP w0.152: Y1.3 46.7,23.65 SH44.2 C22.1
N23486779: length 2.3
  TOP w0.152: U4.6 36.79,35.64 v1(36.79,36.86)
  BOTTOM w0.152: TP108.1 v1(36.79,36.86)
N23497733: length 3.6
  TOP w0.508: C34.2 30.7,44.22 v1(28.92,44.22) 28.41,43.71 U7.5
N23735993: length 16.2
  TOP w0.381: v1(27.97,14.12) 27.9,14.19 R140.2
  BOTTOM w0.381: J3.10 32.98,3.84 32.98,6.38 30.44,8.92 30.44,11.71 29.93,12.22 28.41,12.22 27.97,12.66 v1(27.97,14.12)
N23736069: length 6
  TOP w0.152: v1(30.44,6.63) 30.44,3.84 J3.6
  BOTTOM w0.152: v1(30.44,6.63) 30.44,7.3 30.25,7.49 SH13.1
N23818123: length 5.4
  TOP w0.813: J7.3 24.11,10.69 24.11,13.74 ; C40.1 24.11,13.74 ; 24.11,13.74 D6.A
N23859389: length 3
  TOP w0.152: R122.2 56.1,46.5 v1(56.11,46.52)
  BOTTOM w0.152: v1(56.11,46.52) 56.11,47.22 J1.3
N23859394: length 3.8
  TOP w0.152: R123.2 v1(53.05,46.57)
  BOTTOM w0.152: J1.5 54.64,47.08 54.13,46.57 v1(53.05,46.57)
N23859399: length 5.1
  TOP w0.152: R129.2 v1(49.24,46.51)
  BOTTOM w0.152: v1(49.24,46.51) 51.52,46.51 52.1,47.08 J1.7
N23868552: length 27
  TOP w0.152: U1.13 43.25,13.66 43.01,13.42 v1(43.01,12.6)
  BOTTOM w0.152: J42.2 55.38,28.01 55.38,26.26 54.98,25.85 50.43,25.85 49.43,24.85 49.43,21.11 47.4,19.08 47.4,15.52 44.98,13.11 43.52,13.11 v1(43.01,12.6)
N23868554: length 30.2
  TOP w0.152: v1(43.71,12.6) 43.71,12.6 U1.14
  BOTTOM w0.152: v1(43.71,12.6) 45.87,12.6 47.93,14.66 47.93,15.19 48.81,16.06 48.81,17.54 48.57,17.77 48.57,18.22 49.01,18.65 49.01,19.86 50.05,20.9 50.05,24.37 50.31,24.63 54.57,24.63 55.36,25.43 56.26,25.43 57.92,27.09 57.92,30.56 J41.1
N23869363: length 6.1
  TOP w0.254: C36.1 40.26,20.81 43.53,20.81 44.05,20.29 U1.56
  TOP w0.508: R9.1 C36.1
N23870337: length 3.7
  TOP w0.203: L9.2 L11.2 C15.1 C13.1
N23870339: length 2.4
  TOP w0.203: C11.2 L5.1 55.72,15.39 C46.1 55.71,15.39 C13.2
N23870349: length 3.3
  TOP w0.203: C7.2 L2.1 58.01,15.39 C9.1 57.99,15.39 L5.2 C11.1
N23870369: length 3.3
  TOP w0.203: C8.1 L3.2 57.24,21.11 C3.1 58.76,21.11 L1.1 C1.2
N23870499: length 2.9
  TOP w0.203: C10.1 C12.2 L10.2 L12.2
N23870540: length 2.4
  TOP w0.203: C10.2 55.71,21.11 C45.1 56.48,21.11 L3.1 C8.2
N23886926: length 3.8
  TOP w0.152: R130.2 v1(47.71,46.51)
  BOTTOM w0.152: J1.9 49.56,47.46 49.11,47.02 48.22,47.02 v1(47.71,46.51)
N23887030: length 2.9
  TOP w0.152: R131.2 v1(46.19,46.51)
  BOTTOM w0.152: v1(46.19,46.51) 47.02,47.33 J1.11
N23913269: length 27.4
  TOP w0.152: v1(39.22,15.62) 40.45,15.62 R85.2 ; J31.2 52.1,28.98 50.46,27.34 40.13,27.34 v1(40,27.47)
  BOTTOM w0.152: v1(39.22,15.62) 38.96,15.88 38.96,26.42 v1(40,27.47)
N23918308: length 3.1
  TOP w0.381: 12.92,40.18 v1(12.92,39.33)
  TOP w0.508: D18.A 11.86,40.18 L6.2
N23923482: length 7.5
  TOP w0.152: R136.2 43.4,6.46 43.68,6.18 43.68,3.97 45.08,2.57 J4.2
N23926816: length 2.3
  TOP w0.152: U3.3 v1(21.3,19.39)
  BOTTOM w0.152: v1(21.3,19.39) TP3.1
N23926819: length 1.6
  TOP w0.152: v1(22.31,21.62) 21.7,21.62 U3.6
  BOTTOM w0.152: TP5.1 v1(22.31,21.62)
N23926865: length 3.5
  TOP w0.152: R19.1 22.57,18.82 22.82,19.08 v1(22.82,19.39) 22.82,20.6 22.57,20.85 U3.5
N23927016: length 2.2
  TOP w0.152: R18.1 19.71,26.63 D5.A
N23933963: length 3.9
  TOP w0.152: U4.5 36.17,33.95 R12.1 v1(36.79,33.81)
  BOTTOM w0.152: v1(36.79,33.81) TP107.1
N23941230: length 50.5
  TOP w0.152: v1(41.87,29.74) 41.87,29.61 41.25,28.99 Q1.D2 ; v1(40.09,42.19) R121.2 40.09,40.16 R126.2 38.95,39.01 38.95,37.24 v1(39.33,36.86)
  BOTTOM w0.152: J2.18 18.88,49.54 18.88,46.89 19.34,46.43 22.28,46.43 22.74,46.9 28.66,46.9 28.98,47.22 28.98,49.05 29.43,49.49 36.28,49.49 36.66,49.11 36.66,47.46 37.05,47.08 37.05,44.35 37.87,43.52 39.52,43.52 40.09,42.95 v1(40.09,42.19) ; v1(41.87,29.74) 41.96,29.83 41.96,32.26 41.59,32.63 41.2,32.63 40.6,33.24 40.6,36.54 40.28,36.86 v1(39.33,36.86)
N23941233: length 46.3
  TOP w0.152: v1(39.84,32.03) 39.95,31.92 Q1.D1 ; v1(39.33,36.09) 38.57,36.86 v1(38.57,42.95) R120.2 40.09,44.22 R125.2
  BOTTOM w0.152: v1(39.84,32.03) 39.84,35.59 v1(39.33,36.09) ; v1(38.57,42.95) 37.87,42.95 36.66,44.16 36.66,46.44 36.03,47.08 30.06,47.08 29.47,46.49 22.91,46.49 22.55,46.13 17.1,46.13 16.34,46.89 16.34,49.54 J2.20
N23941622: length 2.3
  TOP w0.152: v1(44.67,37.55) 44.71,37.51 U16.4
  BOTTOM w0.152: SH6.1 v1(44.67,37.55)
N23941631: length 2.8
  TOP w0.152: U16.7 46.66,37.21 46.51,37.36 46.13,37.36 v1(45.94,37.55)
  BOTTOM w0.152: SH3.1 v1(45.94,37.55)
N23941634: length 2.3
  TOP w0.152: v1(47.21,37.55) 47.31,37.45 U16.8
  BOTTOM w0.152: SH7.1 v1(47.21,37.55)
N23941637: length 2.6
  TOP w0.152: v1(48.48,37.55) 48.29,37.36 48.09,37.36 47.96,37.23 U16.9
  BOTTOM w0.152: SH1.1 v1(48.48,37.55)
N23943103: length 2.9
  TOP w0.152: v1(53.87,38.32) 53.87,36.33 U17.1
  BOTTOM w0.152: SH8.1 v1(53.87,38.32)
N23943106: length 6.4
  TOP w0.152: U17.3 55.23,35.23 54.95,34.95 53.3,34.95 53.05,35.2 v1(53.05,37.36)
  BOTTOM w0.152: SH9.1 v1(53.05,37.36)
N23943109: length 3.9
  TOP w0.152: U17.4 55.88,37.02 55.17,37.73 55.17,37.97 v1(55.14,38)
  BOTTOM w0.152: v1(55.14,38) 55.14,36.8 54.94,36.6 SH10.1
N23943112: length 2.5
  TOP w0.152: v1(56.1,37.62) 56.53,37.18 U17.5
  BOTTOM w0.152: SH11.1 v1(56.1,37.62)
N23943115: length 2.5
  TOP w0.152: v1(57.62,37.62) 57.18,37.18 U17.6
  BOTTOM w0.152: SH12.1 v1(57.62,37.62)
N23943118: length 4.2
  TOP w0.152: U17.7 57.81,36.27 57.81,35.14 58.13,34.82 v1(58.38,34.82)
  BOTTOM w0.152: v1(58.38,34.82) 58.38,36.35 58.64,36.6 SH14.1
N23943121: length 6.9
  TOP w0.152: U17.8 58.48,37.15 59.97,38.63 61.68,38.63 v1(62.19,38.13)
  BOTTOM w0.152: SH15.1 v1(62.19,38.13)
N23943124: length 4.4
  TOP w0.152: v1(60.67,38.13) 59.97,38.13 59.13,37.29 U17.9
  BOTTOM w0.152: SH16.1 v1(60.67,38.13)
N23943348: length 2.8
  TOP w0.152: U16.20 42.76,43.02 42.57,43.21 v1(42.06,43.21) 41.36,43.21 R120.1
N23943351: length 5.5
  TOP w0.152: U16.18 44.06,41.07 43.87,40.89 42.56,40.89 42.32,41.12 42.32,41.72 41.85,42.19 v1(41.3,42.19) 41.11,42 R121.1
N23958500: length 2.4
  TOP w0.152: U16.1 42.76,35.58 42.51,35.33 v1(41.94,35.33) R118.2
N23958507: length 4.5
  TOP w0.152: U16.3 44.06,37.21 43.78,37.49 42.19,37.49 41.94,37.24 v1(41.94,36.86) R119.2
N23972508: length 39.9
  TOP w0.457: C47.2 64.1,21.11 arc(64.46,21.26) 64.6,21.62 64.6,40.41 arc(66.8,45.71) 72.1,47.9 J48.1
N23972666: length 20.3
  TOP w0.457: C58.2 67.28,10.18 arc(68.69,6.77) 72.1,5.36 J49.1
N23977839: length 17
  TOP w0.635: R3.1 18.76,13.79 ; 18.76,13.79 17.28,13.79 U18.1 ; 18.76,13.79 C55.1
  TOP w0.813: D1.C 23.08,7.9 J8.3 C55.1 22.31,13.79 D10.C
N23977884: length 4.6
  TOP w0.813: D2.C TP33.1 v1(17.74,9.04) J8.2
  BOTTOM w0.508: TP33.1 v1(17.74,9.04)
N23977917: length 41.4
  TOP w0.813: J45.2 11.14,19.84 v1(11.14,18.95) R6.2 11.14,15.77 D3.C 9.74,15.77 9.11,15.14 9.11,12.6 9.74,11.96 10.88,11.96 ; 10.88,11.96 J46.2 ; 10.88,11.96 R1.2
  BOTTOM w0.508: R6.2 v1(11.14,18.95)
  BOTTOM w0.762: J40.2 J47.2
  BOTTOM w0.813: J45.2 14.31,20.6 15.58,19.33 15.58,16.66 16.73,15.52 23.96,15.52 25.36,16.92 J40.2
N23977919: length 3.1
  TOP w0.813: J8.1 13.93,11.96 R1.1
N23978170: length 2.7
  TOP w0.813: D7.C v1(13.74,17.81) R6.1
N23978250: length 5.6
  TOP w0.152: R10.1 v1(11.39,24.79) 8.6,24.79 8.34,25.04 D4.C
  BOTTOM w0.152: v1(11.39,24.79) 10.12,24.79 TP8.1
N23978332: length 1.7
  TOP w0.305: U18.3 18.32,15.71 R3.2
N23978342: length 4.6
  TOP w0.508: U18.4 15.52,15.71 16.6,16.79 v1(17.87,16.79) C56.1
N23993054: length 4.6
  TOP w0.152: R11.1 v1(32.47,31.52) 32.47,30.93 32.04,30.49 D17.1
  BOTTOM w0.152: v1(32.47,31.52) 33.24,31.52 TP18.1
N23993056: length 4.5
  TOP w0.152: D17.4 35.38,30.49 v1(35.39,30.51) 35.39,31.9 R28.1
  BOTTOM w0.152: v1(35.39,30.51) TP19.1
N23993058: length 3.8
  TOP w0.152: D17.3 35.38,28.99 v1(35.39,28.98) 36.28,28.98 R29.1
  BOTTOM w0.152: v1(35.39,28.98) TP20.1
N24008143: length 6.6
  TOP w0.152: R128.1 v1(19.65,47.02)
  BOTTOM w0.152: J2.16 21.42,49.54 21.42,47.46 20.98,47.02 v1(19.65,47.02)
N24082518: length 4.5
  TOP w0.152: Y4.7 57.39,11.41 v1(56.67,10.69) 56.48,10.88 54.38,10.88 R96.2
N24091032: length 9.4
  TOP w0.457: C67.1 67.27,24.79 ; 67.27,24.79 C50.2 ; 67.27,24.79 L4.1
N24091265: length 3.9
  TOP w0.457: ANT1.2 C68.1 67.27,26.31 L4.2
N24125287: length 1.9
  TOP w0.152: v1(42.63,19.71) 42.7,19.65 43.71,19.65 U1.1
  BOTTOM w0.152: SH42.2 v1(42.63,19.71)
N24125299: length 3.8
  TOP w0.152: U1.2 42.17,19.16 41.62,19.71 v1(40.98,19.71)
  BOTTOM w0.152: v1(40.98,19.71) SH43.2
N24162373: length 2.5
  TOP w0.152: U5.6 6.2,26.08 v1(6.57,26.44)
  BOTTOM w0.152: v1(6.57,26.44) TP15.1
N24162382: length 3
  TOP w0.152: U5.5 6.82,24.92 7.07,25.17 7.07,25.68 v1(7.84,26.44) R20.1
N24162397: length 53.3
  TOP w0.152: U5.2 5.4,23.76 5.3,23.65 R21.2 v1(4.53,22.63) 4.53,23.14 4.22,23.46 2.31,23.46 1.99,23.14 1.99,19.65 2.44,19.2 3.45,19.2 3.84,18.82 v1(3.84,11.96) ; R124.2 4.79,27.2 4.53,26.95 v1(4.53,26.44) ; v1(16.66,11.96) 18.44,11.96 18.95,11.46 18.95,9.74 19.39,9.3 20.35,9.3 23.01,6.63 v1(29.11,6.63)
  BOTTOM w0.152: SH13.2 29.11,7.84 v1(29.11,6.63) ; v1(4.53,26.44) v1(4.53,22.63) ; v1(3.84,11.96) v1(16.66,11.96)
N24165182: length 17.5
  TOP w0.762: D12.A 17.74,2.57 16.73,2.57 R127.2
  TOP w0.813: D12.A 19.41,0.91 30.06,0.91 J3.8
N24184722: length 7.9
  TOP w0.152: J44.2 45.36,30.43 U16.5
N24184751: length 5
  TOP w0.152: U16.6 46,36.27 45.94,36.21 45.94,32.03 J43.1
N24196405: length 3.7
  TOP w0.152: D8.C v1(38.06,32.03) R30.1
  BOTTOM w0.152: v1(38.06,32.03) TP17.1
N24206241: length 3
  TOP w0.152: R141.2 58.51,46.13 59.71,47.34 59.71,48.28 J1.1
N234833070: length 1.8
  TOP w0.152: D11.A R17.2
N241623790: length 2.5
  TOP w0.152: U5.3 v1(5.8,23.46)
  BOTTOM w0.152: v1(5.8,23.46) 5.8,24.28 TP14.1

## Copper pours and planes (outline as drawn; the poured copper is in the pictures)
GND on BOTTOM (solid shape): 82.26,43.08 77.01,43.08 77.01,45.28 82.26,45.28
GND on BOTTOM (solid shape): 82.26,8.03 77.01,8.03 77.01,10.19 82.26,10.19
GND on BOTTOM (solid shape): 82.38,50.63 77.14,50.63 77.14,52.83 82.38,52.83
GND on BOTTOM (solid shape): 82.38,0.51 77.14,0.51 77.14,2.67 82.38,2.67
GND on TOP: 62.38,22.12 62.38,22.89 60.99,22.89 60.99,22.12
GND on TOP: 77.01,10.19 82.26,10.19 82.26,8.03 77.01,8.03
GND on TOP: 62.38,13.54 62.38,14.31 60.99,14.31 60.99,13.54
GND on TOP: 62.38,16.08 62.38,16.85 60.99,16.85 60.99,16.08
GND on TOP: 44.7,13.56 44.7,19.22 50.4,19.22 50.4,16.6 47.47,16.6 47.47,13.56
GND on TOP: 77.14,2.67 82.38,2.67 82.38,0.51 77.14,0.51
GND on TOP: 77.14,52.83 82.38,52.83 82.38,50.63 77.14,50.63
GND on TOP: 82.38,52.83 82.38,43.08 68.67,43.08 68.67,10.19 82.38,10.19 82.38,0.51 6.35,0.51 2.22,2.22 0.51,6.35 0.51,46.99 2.22,51.12 6.35,52.83 ; 3 cut-outs
GND on TOP: 77.01,45.28 82.26,45.28 82.26,43.08 77.01,43.08
GND on TOP: 62.38,19.51 62.38,20.28 60.99,20.28 60.99,19.51
GND on BOTTOM, GND: 82.38,52.83 82.38,43.08 68.67,43.08 68.67,10.19 82.38,10.19 82.38,0.51 6.35,0.51 2.22,2.22 0.51,6.35 0.51,46.99 2.22,51.12 6.35,52.83
GND on PWR: 62.7,0.51 62.7,52.83 82.38,52.83 82.38,43.08 68.67,43.08 68.67,10.19 82.38,10.19 82.38,0.51
P3V3_BRD on PWR: 82.38,52.83 82.38,43.08 68.67,43.08 68.67,10.19 82.38,10.19 82.38,0.51 6.35,0.51 2.22,2.22 0.51,6.35 0.51,46.99 2.22,51.12 6.35,52.83
SDA_USB_VOUT33 on PWR: 13.04,45.11 36.92,45.11 36.92,32.66 13.04,32.66
SDA_USBSHIELD on TOP: 10.63,31.52 8.34,31.52 8.34,40.41 0.51,40.41 0.51,28.22 10.63,28.22
V_MCU on PWR: 15.07,0.51 15.07,24.92 50.76,24.92 50.76,15.77 57.87,15.77 57.87,10.82 31.2,10.82 31.2,20.09 26.5,20.09 26.5,0.51
V_RF on PWR: 26.76,0.51 26.76,19.84 30.95,19.84 30.95,10.57 58.13,10.57 58.13,16.03 51.02,16.03 51.02,24.92 62.45,24.92 62.45,0.51

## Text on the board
BOTTOM: 170-28745 REV A1 | 7 OF 10 | SECONDARY SIDE
Ref Des/Assembly Bottom: SECONDARY SIDE ASSY
Board Geometry/Soldermask Bottom: 8 OF 10 | SECONDARY SOLDERMASK
Ref Des/Silkscreen Bottom: RF | TP41 | 700-28745 | SCH-28745 | 10 OF 10 | SECONDARY SILKSCREEN
User.Comments: 1 OF 1 | TEST PROBE | 1/1 | 1
TOP: 4 OF 10 | PRIMARY SIDE
Ref Des/Assembly Top: 1 | PRIMARY SIDE ASSY
Board Geometry/Soldermask Top: 3 OF 10 | PRIMARY SOLDERMASK
Ref Des/Silkscreen Top: RST | DEBUG | C | SMA | 1 | SMA PA_BOOST Port | SMA RF_IO Port | 1 OF 10 | PRIMARY SILKSCREEN | FRDM-KW019032
GND: 5 OF 10 | L2_GND
PWR: 6 OF 10 | L3_PWR
DIMENSION: GRID ORIGIN | PRIMARY DATUM
BODY_CENTER: A - TARGET : 10 MILS | B - TARGET : 38 MILS | C - TARGET : 10 MILS | 50 OHMS SINGLE ENDED | TRACE: 18 MILS +/-10% | 23. OVERALL PCB DIELECTRIC THICKNESS ARE TARGETED (A) 10 MILS+/-10%, (B) 38 MILS +/-10% AND (C) 10 MILS +/- 10%. | 22. INTENTIONAL SHORTS AT: | AS SHOWN IN DETAIL 'A'. ADJUSTMENT IN SUBSTRATE B IS ALLOWED TO MEET OVERALL HEIGHT REQUIREMENT. | SH1 N23941637 & PTA0/SWD_CLK | SH3 N23941631 & PTE16/SPIO_PCS0 | SH6 N23941622 & PTE17/SPIO_SCK | SH7 N23941634 & PTA3/SWD_DIO | SH8 N23943103 & PTD7 | SH9 N23943106 & PTC2 | SH10 N23943109 & PTC1 | SH12 N23943115 & PTB2/UART0_RTS | SH13 N23736069 & N23952324 | SH14 N23943118 & PTB17/UART0_CTS | SH15 N23943121 & PTA1/UART0_RX | SH16 N23943124 & PTA2/UART0_TX | SH40 PTC3 & DIO0 | SH41 PTC4 & DIO1 | SH42 N24125287 & V_MCU | SH43 N24125299 & GND | SH44 N23353504 & XTAL_32M | SH45 PTA18 & DIO5/CLKOUT | J10 PTD4 & DIO4 | J11 RESET_B_TGTMCU & SDA_RST_TGTMCU-J_B | J40 N23977915 & V_RF | J45 N23977915 & P3V3_BRD | J46 N23977915 & P3V3 | J47 N23977915 & V-RF | Er - MUST BE FROM 4.2 TO 4.4 | 23 | 16 | 17 | 8 | 0.062 +/- 10% | DETAIL B
DISPLAY_TOP: 2 OF 10 | PASTEMASK TOP
USER_PART_NUM_TOP: 9 OF 10 | SECONDARY PASTEMASK
User.14: A. QUIROZ | B. KUHAR | 01/20/16 | 06/29/15 | A.Q | A | SILK UPDATES, INITIAL PRODUCTION
User.17: Trace Width | (Mils) | Trace Spacing | "Airgap" | Impedance | (Ohms) | L4_SS | 11.5 | 5.50 | 90 | Differential
User.20: FIGURE | SIZE | 8.0 | 10.0 | 18.0 | 31.0 | 40.0 | 42.0 | 63.0 | 35.0 | 125.0 | DRILL CHART: TOP to BOTTOM | ALL UNITS ARE IN MILS | TOLERANCE | +0.0/-8.0 | +2.0/-10.0 | +2.0/-18.0 | +2.0/-2.0 | +3.0/-3.0 | PLATED | NON-PLATED | QTY | 8 | 653 | 2 | 20 | 41 | 64 | 1 | 4
